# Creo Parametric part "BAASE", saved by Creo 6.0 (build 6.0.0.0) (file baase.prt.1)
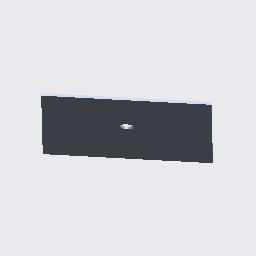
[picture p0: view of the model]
Units: millimeter Newton Second (mmNs); MM, TONNE, SECS

Created from: MMNS_PART_SOLID.PRT

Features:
  1. datum plane "RIGHT"
  2. datum plane "TOP"
  3. datum plane "FRONT"
  4. coordinate system
  5. sketch "Sketch 1"
  6. extrusion "Extrude 1"

Surfaces: 6 plane, 1 cylinder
